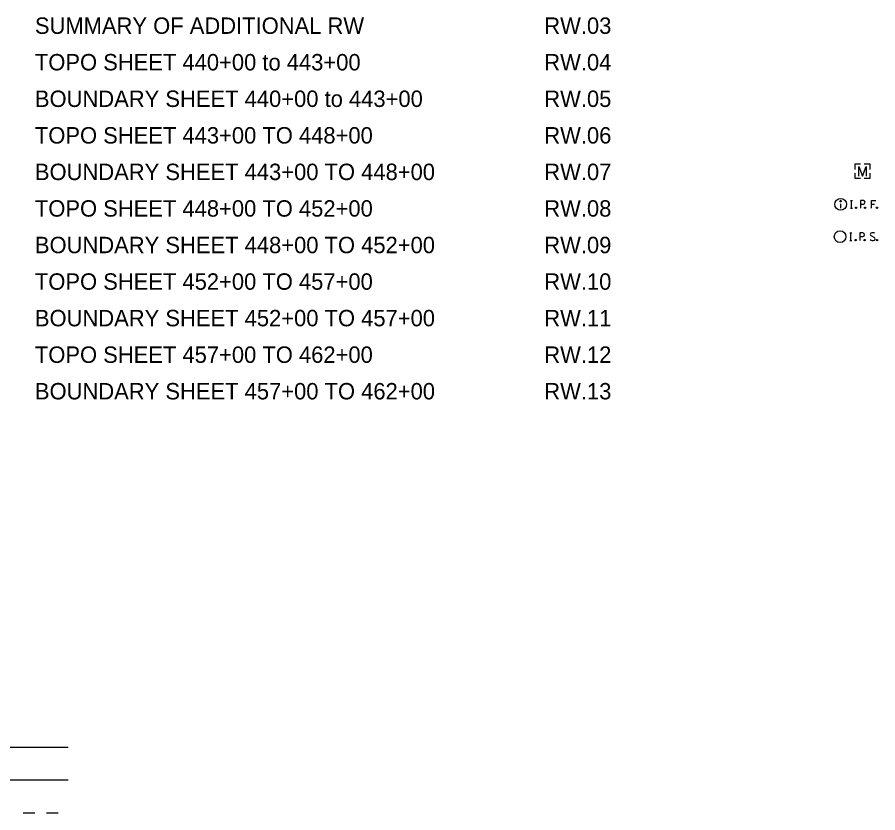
# Model space of a CAD drawing. Extents: x -19 to 40.8, y -1.8 to 26.1.
# Drawn here: x 13.54 to 20.88, y 5.15 to 11.94 of the extents above; entities that cross this region are included whole.
import ezdxf

# ---------------------------------------------------------------- set-up
doc = ezdxf.new("R2010")
doc.units = 0
doc.layers.add('SH_Data', color=7, linetype='Continuous')
doc.layers.add('SH_Text', color=7, linetype='Continuous')

msp = doc.modelspace()

# ---------------------------------------------------------------- linework, layer by layer
at = {"layer": 'SH_Text'}
for p, q in [((20.7517, 10.6297), (20.7517, 10.6297)), ((20.5656, 10.3526), (20.5656, 10.3157)), ((20.649, 10.381), (20.6656, 10.381)), ((20.649, 10.381), (20.6656, 10.381)), ((20.6573, 10.3143), (20.6573, 10.381)), ((20.8276, 10.3143), (20.8276, 10.381)), ((20.8276, 10.381), (20.866, 10.381)), ((20.649, 10.3143), (20.6656, 10.3143)), ((20.734, 10.3491), (20.7606, 10.3491)), ((20.8276, 10.3486), (20.855, 10.3486)), ((20.6446, 10.1045), (20.6613, 10.1045)), ((20.6446, 10.1045), (20.6613, 10.1045)), ((20.653, 10.0379), (20.653, 10.1045)), ((20.7296, 10.0726), (20.7563, 10.0726)), ((20.824, 10.0808), (20.8545, 10.0649)), ((20.6446, 10.0379), (20.6613, 10.0379)), ((10.4913, 5.7144), (13.9747, 5.7144)), ((10.4913, 5.4344), (13.9747, 5.4344)), ((13.5909, 5.1544), (13.6909, 5.1544)), ((13.7909, 5.1544), (13.8909, 5.1544))]:
    msp.add_line(p, q, dxfattribs=at)
for points in [[(20.6892, 10.6455), (20.6892, 10.6923), (20.736, 10.6923)], [(20.7209, 10.588), (20.7209, 10.6714), (20.7517, 10.588), (20.7825, 10.6714), (20.7825, 10.588)], [(20.7665, 10.6923), (20.8143, 10.6923), (20.8143, 10.6455)], [(20.736, 10.5672), (20.6892, 10.5672), (20.6892, 10.6139)], [(20.8143, 10.6139), (20.8143, 10.5672), (20.7665, 10.5672)], [(20.7606, 10.381), (20.734, 10.381), (20.734, 10.3143)], [(20.7563, 10.1045), (20.7296, 10.1045), (20.7296, 10.0379)]]:
    msp.add_lwpolyline(points, dxfattribs=at)
for centre, radius in [((20.5656, 10.3477), 0.05), ((20.5656, 10.3748), 0.00667), ((20.6974, 10.3189), 0.00583), ((20.7741, 10.3189), 0.00583), ((20.8758, 10.3189), 0.00583), ((20.5613, 10.0712), 0.05), ((20.6931, 10.0424), 0.00583), ((20.7698, 10.0424), 0.00583), ((20.8767, 10.042), 0.00583)]:
    msp.add_circle(centre, radius, dxfattribs=at)
for centre, radius, start, end in [((20.7582, 10.365), 0.0162, 278.88026, 81.11974), ((20.7538, 10.0886), 0.0162, 278.88026, 81.11974), ((20.8305, 10.0906), 0.0118, 126.25873, 236.36755), ((20.8402, 10.0695), 0.0349, 61.34633, 118.65367), ((20.8446, 10.054), 0.0148, 311.48833, 47.93584), ((20.8388, 10.0657), 0.0276, 223.66947, 304.39628)]:
    msp.add_arc(centre, radius, start, end, dxfattribs=at)

# ---------------------------------------------------------------- texts
at = {"layer": 'SH_Data'}
for s, p in [('SUMMARY OF ADDITIONAL RW           ', (13.6919, 11.8026)), ('RW.03 ', (18.0375, 11.8026)), ('TOPO SHEET 440+00 to 443+00        ', (13.6919, 11.4906)), ('RW.04 ', (18.0375, 11.4906)), ('BOUNDARY SHEET 440+00 to 443+00    ', (13.6919, 11.1786)), ('RW.05 ', (18.0375, 11.1786)), ('TOPO SHEET 443+00 TO 448+00        ', (13.6919, 10.8666)), ('RW.06 ', (18.0375, 10.8666)), ('BOUNDARY SHEET 443+00 TO 448+00    ', (13.6919, 10.5546)), ('RW.07 ', (18.0375, 10.5546)), ('TOPO SHEET 448+00 TO 452+00        ', (13.6919, 10.2426)), ('RW.08 ', (18.0375, 10.2426)), ('BOUNDARY SHEET 448+00 TO 452+00    ', (13.6919, 9.9306)), ('RW.09 ', (18.0375, 9.9306)), ('TOPO SHEET 452+00 TO 457+00        ', (13.6919, 9.6186)), ('RW.10 ', (18.0375, 9.6186)), ('BOUNDARY SHEET 452+00 TO 457+00    ', (13.6919, 9.3066)), ('RW.11 ', (18.0375, 9.3066)), ('TOPO SHEET 457+00 TO 462+00        ', (13.6919, 8.9946)), ('RW.12 ', (18.0375, 8.9946)), ('BOUNDARY SHEET 457+00 TO 462+00    ', (13.6919, 8.6826)), ('RW.13 ', (18.0375, 8.6826))]:
    msp.add_text(s, height=0.14, dxfattribs=at).set_placement(p)

doc.saveas('drawing.dxf')
